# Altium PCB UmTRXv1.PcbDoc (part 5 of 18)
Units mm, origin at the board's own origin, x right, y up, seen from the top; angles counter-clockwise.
Board outline 172 x 113 mm, 6 copper layers (Top Layer, GND, MidLayer1, Mid-Layer 2, InternalPlane2, Bottom Layer); 766 components, 613 nets, 3008 pads, 1360 vias.
Unrouted connection lines stored in the file: 2.
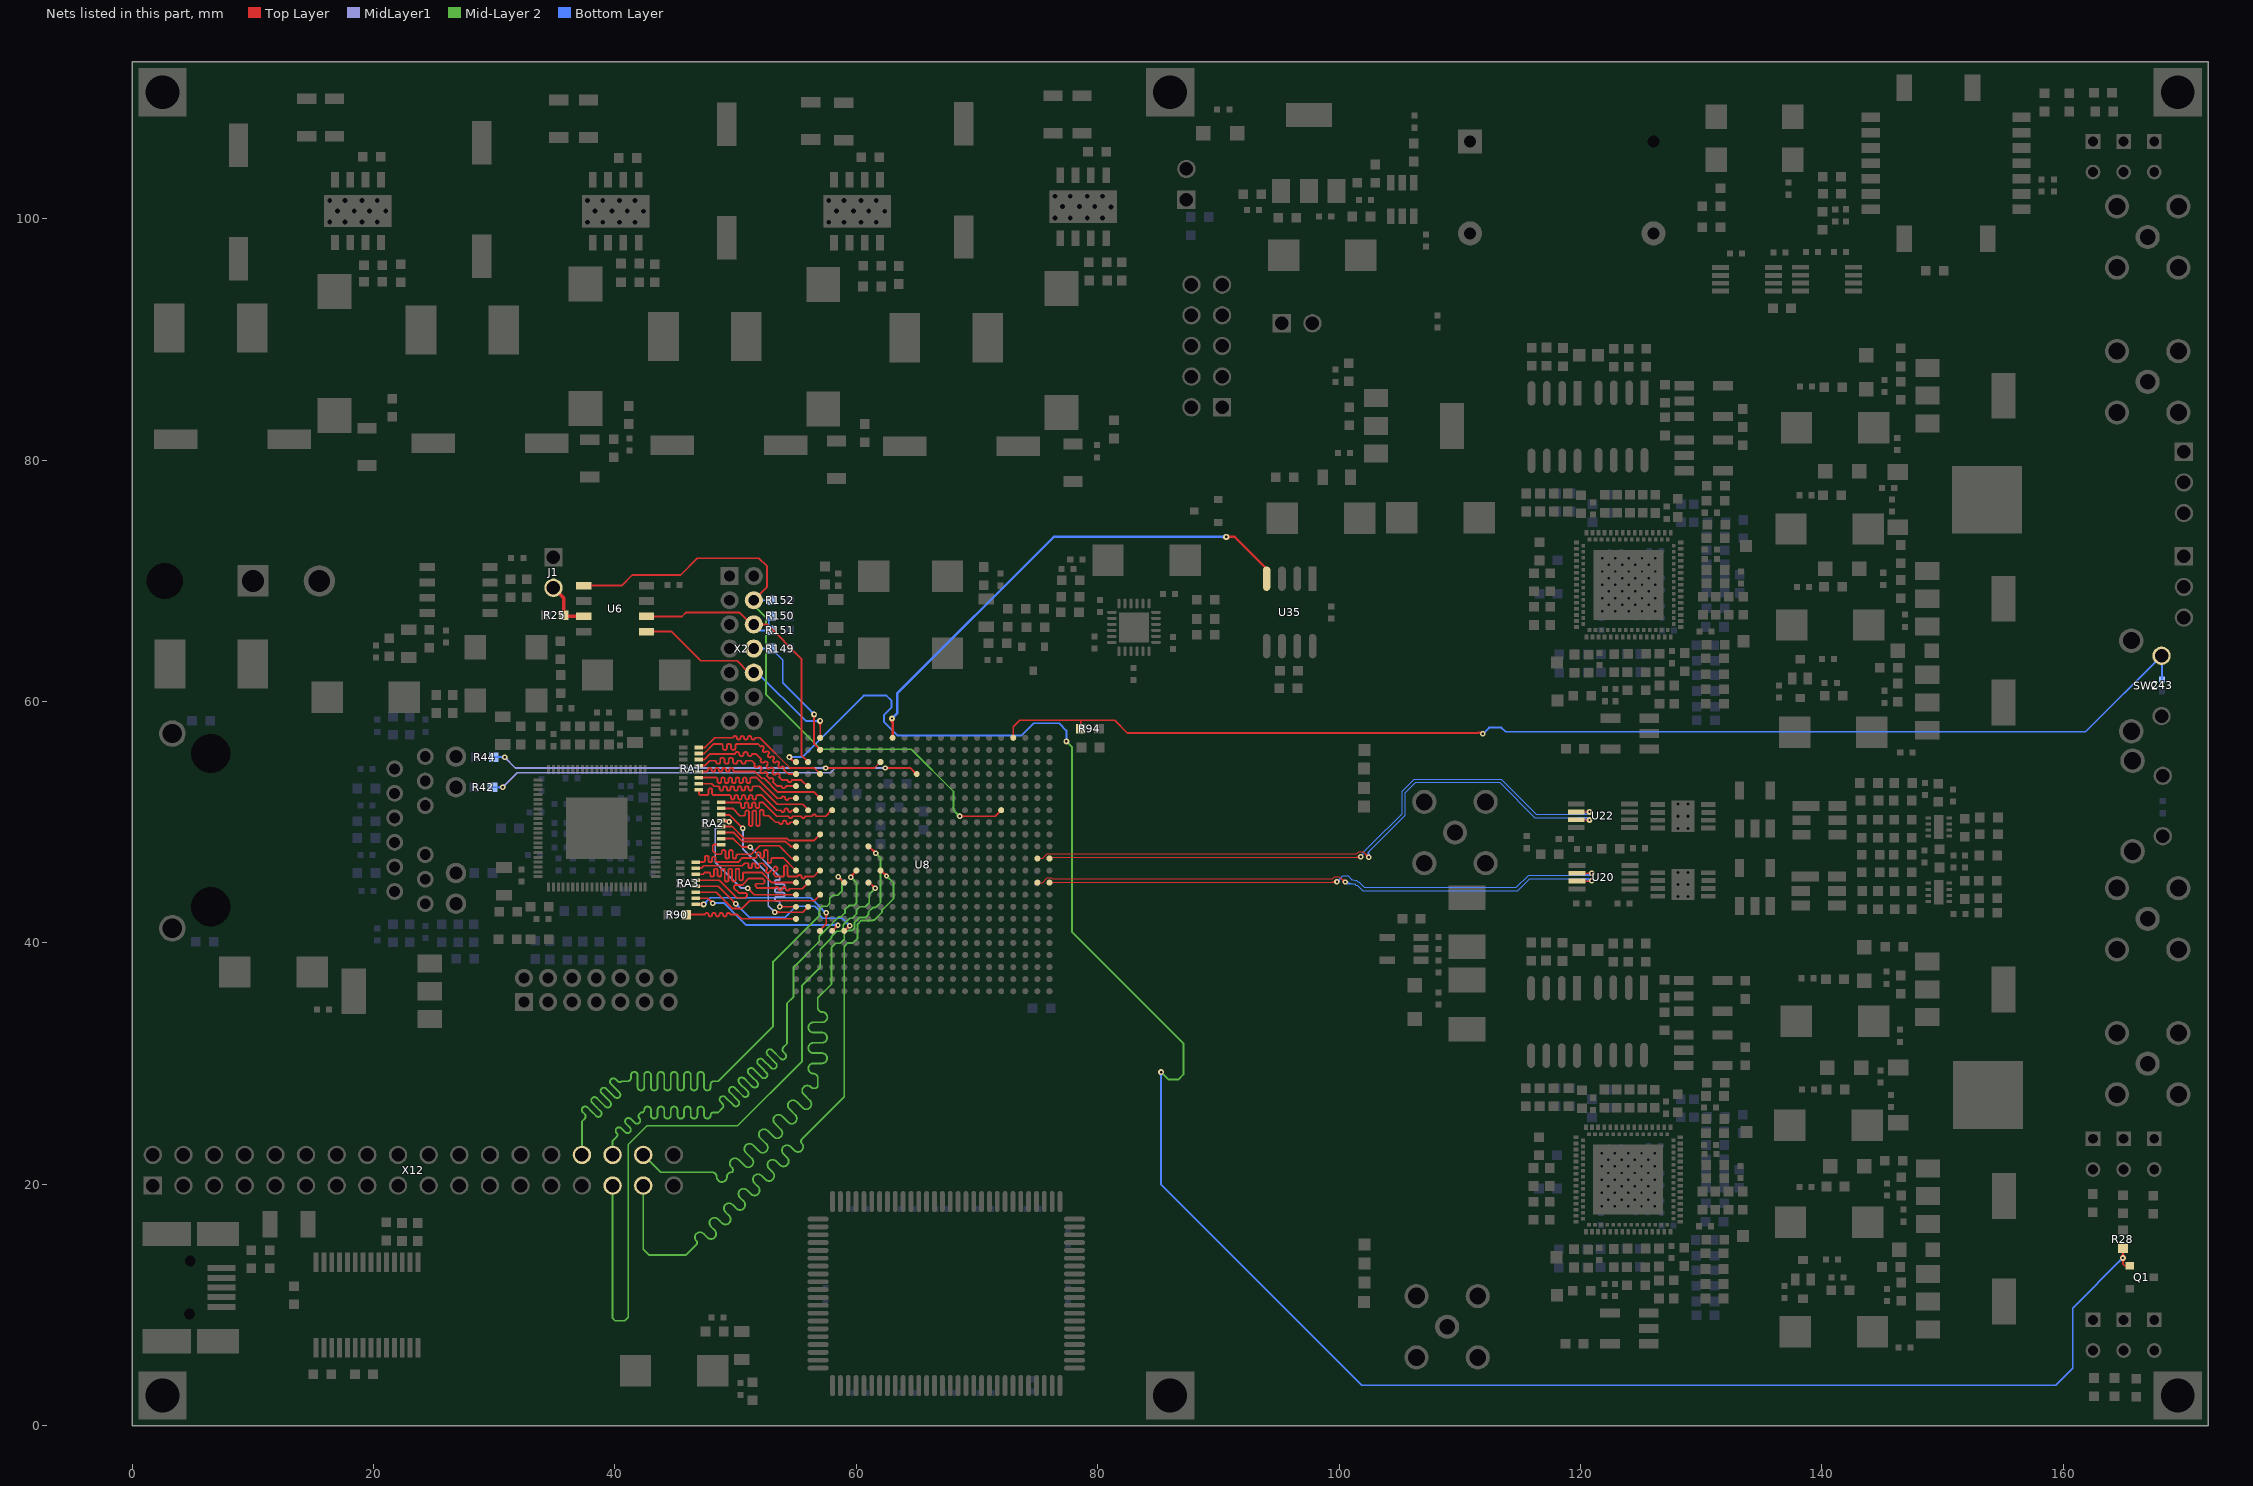
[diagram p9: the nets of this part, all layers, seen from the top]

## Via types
v1: diameter 0.45, hole 0.2, Top Layer to Bottom Layer, tented both sides, 554 vias
v2: diameter 0.5, hole 0.2, Top Layer to Bottom Layer, tented both sides, 468 vias
v3: diameter 0.7, hole 0.3, Top Layer to Bottom Layer, tented both sides, 206 vias
v4: diameter 0.4, hole 0.2, Top Layer to Bottom Layer, tented both sides, 82 vias
v5: diameter 0.8, hole 0.3, Top Layer to Bottom Layer, tented both sides, 16 vias
v6: diameter 0.6, hole 0.25, Top Layer to Bottom Layer, tented both sides, 16 vias
v7: diameter 0.5, hole 0.3, Top Layer to Bottom Layer, tented both sides, 8 vias
v8: diameter 0.7, hole 0.3, Top Layer to Bottom Layer, 4 vias
v9: diameter 0.6, hole 0.3, Top Layer to Bottom Layer, tented both sides, 4 vias
v10: diameter 0.5, hole 0.2, Top Layer to Bottom Layer, 2 vias

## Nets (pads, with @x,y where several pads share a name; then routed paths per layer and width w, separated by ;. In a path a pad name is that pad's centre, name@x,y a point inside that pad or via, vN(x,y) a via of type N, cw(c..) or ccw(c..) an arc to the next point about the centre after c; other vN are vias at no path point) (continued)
DEBUG29: U8.K18 X12.30 | length 63.5
  Top Layer w0.15: v1@58.5,45.35 cw(c58.5,44.988) 58.756,45.244 cw(c59.012,45.5) v1@58.65,45.5 ; v1(58.5,45.5) U8.K18@59,45
  Mid-Layer 2 w0.15: X12.30@37.26,22.44 37.26,25.21 37.489,25.439 ccw(c37.294,25.633) 37.489,25.827 37.332,25.985 cw(c37.526,26.179) 37.332,26.374 cw(c37.526,26.179) 37.72,26.374 38.072,26.022 38.424,25.671 ccw(c38.618,25.865) 38.813,25.671 ccw(c38.618,25.865) 38.813,26.059 38.461,26.411 38.109,26.763 ; 38.109,26.763 cw(c38.304,26.957) 38.109,27.151 cw(c38.304,26.957) 38.498,27.151 39.201,26.448 ; 39.202,26.448 ccw(c39.396,26.643) 39.59,26.448 ccw(c39.396,26.643) 39.591,26.837 38.887,27.54 cw(c39.082,27.735) 38.887,27.929 cw(c39.082,27.735) 39.276,27.929 39.979,27.226 ccw(c40.174,27.421) 40.368,27.226 ccw(c40.174,27.421) 40.368,27.615 39.665,28.318 cw(c39.86,28.513) 39.665,28.707 cw(c39.86,28.513) 40.054,28.707 40.211,28.55 ; 40.211,28.55 ccw(c40.406,28.744) 40.6,28.55 41.05,28.55 ccw(c41.05,28.825) 41.325,28.825 41.325,29.047 cw(c41.6,29.047) 41.6,29.322 cw(c41.6,29.047) 41.875,29.047 41.875,28.053 ccw(c42.15,28.053) 42.15,27.778 ccw(c42.15,28.053) 42.425,28.053 42.425,29.047 cw(c42.7,29.047) 42.7,29.322 cw(c42.7,29.047) 42.975,29.047 42.975,28.053 ccw(c43.25,28.053) 43.25,27.778 ccw(c43.25,28.053) 43.525,28.053 43.525,29.047 cw(c43.8,29.047) 43.8,29.322 cw(c43.8,29.047) 44.075,29.047 44.075,28.053 ccw(c44.35,28.053) 44.35,27.778 ccw(c44.35,28.053) 44.625,28.053 44.625,29.047 cw(c44.9,29.047) 44.9,29.322 cw(c44.9,29.047) 45.175,29.047 45.175,28.053 ccw(c45.45,28.053) 45.45,27.778 ccw(c45.45,28.053) 45.725,28.053 45.725,29.047 cw(c46,29.047) 46,29.322 cw(c46,29.047) 46.275,29.047 46.275,28.053 ccw(c46.55,28.053) 46.55,27.778 ccw(c46.55,28.053) 46.825,28.053 46.825,29.047 cw(c47.1,29.047) 47.1,29.322 cw(c47.1,29.047) 47.375,29.047 47.375,28.053 ccw(c47.65,28.053) 47.65,27.778 ccw(c47.65,28.053) 47.925,28.053 47.925,28.275 cw(c48.2,28.275) 48.2,28.55 48.55,28.55 53.1,33.1 53.1,38.454 56.95,42.304 56.95,42.85 57.15,43.05 57.566,43.05 57.803,43.287 57.803,43.703 58.05,43.95 58.466,43.95 58.8,44.284 58.8,45.2 v1(58.5,45.5) ; v1@58.5,45.35 cw(c58.5,44.988) 58.756,45.244 cw(c59.012,45.5) v1@58.65,45.5
DEBUG30: U8.K16 X12.31 | length 63.4
  Top Layer w0.15: U8.K16@61.05,45.05 v1(61.55,44.55) ; v1@61.4,44.55 ccw(c61.038,44.55) 61.294,44.806 ccw(c61.55,45.062) v1@61.55,44.7
  Mid-Layer 2 w0.15: X12.31@39.8,19.9 39.8,8.9 40,8.7 40.8,8.7 41.1,9 41.1,23.3 42.65,24.85 50.15,24.85 55.5,30.2 55.5,36.5 57,38 57,39.484 57.95,40.434 57.95,40.551 58.378,40.979 58.687,40.979 58.921,41.213 58.921,41.522 59.449,42.05 59.651,42.05 60,42.399 60,42.7 60.3,43 60.75,43 61.075,43.325 61.075,44.025 61.6,44.55 v1(61.55,44.55) ; 61.259,44.209 ccw(c60.917,44.55) v1@61.4,44.55 ; 61.379,44.329 cw(c61.55,44.159) v1@61.55,44.4
DEBUG31: U8.L17 X12.32 | length 62.9
  Top Layer w0.15: v1@59.5,45.45 v1(59.55,45.45) ; v1@59.525,45.525 U8.L17@60,46 ; v1@59.7,45.45 cw(c60.304,45.45) U8.L17@59.877,45.877
  Mid-Layer 2 w0.15: X12.32@39.8,22.44 39.8,23.6 40.135,23.935 ccw(c39.976,24.094) 40.135,24.254 cw(c40.33,24.448) 40.135,24.642 cw(c40.33,24.448) 40.524,24.643 40.842,24.324 ccw(c41.037,24.519) 41.231,24.324 ccw(c41.037,24.519) 41.232,24.713 40.913,25.031 cw(c41.108,25.226) 40.913,25.42 cw(c41.108,25.226) 41.302,25.42 41.62,25.102 ccw(c41.815,25.297) 42.009,25.102 ccw(c41.815,25.297) 42.009,25.491 cw(c42.168,25.65) 42.009,25.809 42.15,25.95 42.2,25.95 ccw(c42.2,26.175) 42.425,26.175 cw(c42.7,26.175) 42.7,26.45 cw(c42.7,26.175) 42.975,26.175 42.975,25.725 ccw(c43.25,25.725) 43.25,25.45 ccw(c43.25,25.725) 43.525,25.725 43.525,26.175 cw(c43.8,26.175) 43.8,26.45 cw(c43.8,26.175) 44.075,26.175 44.075,25.725 ccw(c44.35,25.725) 44.35,25.45 ccw(c44.35,25.725) 44.625,25.725 44.625,26.175 cw(c44.9,26.175) 44.9,26.45 cw(c44.9,26.175) 45.175,26.175 45.175,25.725 ccw(c45.45,25.725) 45.45,25.45 ccw(c45.45,25.725) 45.725,25.725 45.725,26.175 cw(c46,26.175) 46,26.45 cw(c46,26.175) 46.275,26.175 46.275,25.725 ccw(c46.55,25.725) 46.55,25.45 ccw(c46.55,25.725) 46.825,25.725 46.825,26.175 cw(c47.1,26.175) 47.1,26.45 cw(c47.1,26.175) 47.375,26.175 47.375,25.725 ccw(c47.65,25.725) 47.65,25.45 ccw(c47.65,25.725) 47.925,25.725 cw(c48.15,25.725) 48.15,25.95 48.55,25.95 48.9,26.3 ccw(c48.706,26.494) 48.9,26.689 48.75,26.838 cw(c48.945,27.033) 48.75,27.227 cw(c48.945,27.033) 49.139,27.228 ; 49.139,27.227 49.827,26.539 ccw(c50.022,26.734) 50.216,26.539 ccw(c50.022,26.734) 50.216,26.928 ; 50.216,26.928 49.528,27.616 cw(c49.723,27.811) 49.528,28.005 cw(c49.723,27.811) 49.917,28.005 50.605,27.317 ccw(c50.8,27.512) 50.994,27.317 ccw(c50.8,27.512) 50.994,27.706 50.306,28.394 cw(c50.501,28.589) 50.306,28.783 cw(c50.501,28.589) 50.695,28.783 51.039,28.439 51.383,28.095 ccw(c51.577,28.289) 51.772,28.095 ccw(c51.577,28.289) 51.772,28.484 ; 51.473,29.561 51.817,29.217 52.161,28.873 ccw(c52.355,29.067) 52.55,28.873 ccw(c52.355,29.067) 52.55,29.262 52.206,29.606 51.862,29.95 cw(c52.056,30.144) 51.862,30.339 cw(c52.056,30.144) 52.25,30.339 52.939,29.651 ccw(c53.133,29.845) 53.328,29.651 ccw(c53.133,29.845) 53.328,30.039 52.64,30.728 ; 51.473,29.561 ccw(c51.278,29.366) 51.084,29.561 ccw(c51.278,29.366) 51.084,29.172 51.428,28.828 51.772,28.484 ; 52.639,30.728 cw(c52.834,30.922) 52.64,31.116 cw(c52.834,30.922) 53.028,31.117 ; 53.028,31.116 53.716,30.428 ; 53.717,30.428 ccw(c53.911,30.623) 54.105,30.428 ccw(c53.911,30.623) 54.106,30.817 53.956,30.967 cw(c54.15,31.161) 53.956,31.356 54.25,31.65 54.25,35 54.8,35.55 54.8,38 56.925,40.125 56.925,40.55 58.525,42.15 58.716,42.15 59.05,42.484 59.05,42.75 59.4,43.1 59.8,43.1 60,43.3 60,45 v1(59.55,45.45) ; v1@59.55,45.3 cw(c59.55,44.938) 59.806,45.194 cw(c60.062,45.45) v1@59.7,45.45
DEBUG_CLK0: U8.L15 X12.33 | length 63.2
  Top Layer w0.15: U8.L15@62.025,46.025 v1(62.5,45.55) ; v1@62.35,45.55 ccw(c61.988,45.55) 62.244,45.806 ccw(c62.5,46.062) v1@62.5,45.7
  Mid-Layer 2 w0.15: X12.33@42.34,19.9 42.34,14.61 42.8,14.15 45.9,14.15 46.741,14.991 ccw(c46.582,15.151) 46.741,15.31 cw(c47.042,15.61) 46.741,15.911 cw(c47.042,15.61) 47.342,15.911 47.502,15.752 47.656,15.597 ccw(c47.957,15.897) 48.258,15.597 ccw(c47.957,15.897) 48.258,16.198 47.948,16.508 cw(c48.248,16.808) 47.948,17.109 cw(c48.248,16.808) 48.549,17.109 48.704,16.954 48.859,16.799 ccw(c49.159,17.099) 49.46,16.799 ccw(c49.159,17.099) 49.46,17.4 49.15,17.71 cw(c49.45,18.01) 49.15,18.311 cw(c49.45,18.01) 49.751,18.311 49.906,18.156 50.061,18.001 ccw(c50.361,18.301) 50.662,18.001 ccw(c50.361,18.301) 50.662,18.602 50.352,18.912 cw(c50.652,19.212) 50.352,19.513 cw(c50.652,19.212) 50.953,19.513 51.108,19.358 51.263,19.203 ccw(c51.563,19.503) 51.864,19.203 ccw(c51.563,19.503) 51.864,19.804 51.554,20.114 cw(c51.854,20.414) 51.554,20.715 cw(c51.854,20.414) 52.155,20.715 52.31,20.56 52.465,20.405 ccw(c52.765,20.706) 53.066,20.405 ccw(c52.765,20.706) 53.066,21.006 52.756,21.316 cw(c53.057,21.616) 52.756,21.917 cw(c53.057,21.616) 53.357,21.917 53.667,21.607 ccw(c53.967,21.908) 54.268,21.607 ccw(c53.967,21.908) 54.268,22.208 54.113,22.363 53.958,22.518 cw(c54.259,22.818) 53.958,23.119 cw(c54.259,22.818) 54.559,23.119 54.869,22.809 ccw(c55.169,23.11) 55.47,22.809 ccw(c55.169,23.11) 55.474,23.407 ; v1@62.5,45.4 cw(c62.5,45.038) 62.756,45.294 cw(c63.012,45.55) v1@62.65,45.55 ; v1(62.5,45.55) 63.075,44.975 63.075,43.676 62.125,42.726 62.125,42.559 61.466,41.9 61.384,41.9 61.334,41.85 60.384,41.85 60.1,41.566 60.1,40.4 59.7,40 59.3,40 59,39.7 59,27.25 55.474,23.724 ccw(c55.633,23.565) 55.471,23.41 ; 55.471,23.41 ccw(c55.633,23.565) 55.474,23.407 ; 55.471,23.41 cw(c55.169,23.11) 55.474,23.407 ; 55.471,23.41 55.474,23.407
DEBUG_CLK1: U8.N16 X12.34 | length 63.2
  Top Layer w0.15: U8.N16@61.025,48.025 v1(61.6,47.45) ; v1@61.45,47.45 ccw(c61.088,47.45) 61.344,47.706 ccw(c61.6,47.962) v1@61.6,47.6
  Mid-Layer 2 w0.15: X12.34@42.34,22.44 43.78,21 48.05,21 cw(c48.05,20.625) 48.425,20.625 ccw(c48.85,20.625) 48.85,20.2 ccw(c48.85,20.625) 49.275,20.625 cw(c49.65,20.625) 49.65,21 49.7,21 ccw(c49.512,21.188) 49.7,21.376 49.638,21.438 cw(c49.938,21.739) 49.638,22.039 cw(c49.938,21.739) 50.239,22.039 50.739,21.539 ccw(c51.04,21.839) 51.34,21.539 ccw(c51.04,21.839) 51.34,22.14 50.84,22.64 cw(c51.14,22.941) 50.84,23.242 cw(c51.14,22.941) 51.441,23.242 51.942,22.741 ccw(c52.242,23.041) 52.543,22.741 ccw(c52.242,23.041) 52.543,23.342 52.042,23.843 cw(c52.342,24.143) 52.042,24.444 cw(c52.342,24.143) 52.643,24.444 53.144,23.943 ccw(c53.444,24.243) 53.745,23.943 ccw(c53.444,24.243) 53.745,24.544 53.494,24.794 53.244,25.045 cw(c53.544,25.345) 53.244,25.646 cw(c53.544,25.345) 53.845,25.646 54.346,25.145 ccw(c54.646,25.445) 54.947,25.145 ccw(c54.646,25.445) 54.947,25.746 54.446,26.247 cw(c54.746,26.547) 54.446,26.848 cw(c54.746,26.547) 55.047,26.848 55.548,26.347 ccw(c55.848,26.648) 56.149,26.347 ccw(c55.848,26.648) 56.149,26.948 55.633,27.464 cw(c55.934,27.764) 55.633,28.065 cw(c55.934,27.764) 56.234,28.065 ccw(c56.499,28.33) 56.765,28.065 56.8,28.1 56.8,28.8 ccw(c56.425,28.8) 56.425,29.175 ; 56.429,29.175 56.442,29.175 ; 56.446,29.175 cw(c56.446,29.6) 56.021,29.6 cw(c56.446,29.6) 56.446,30.025 57.154,30.025 ccw(c57.154,30.45) 57.579,30.45 ccw(c57.154,30.45) 57.154,30.875 56.446,30.875 cw(c56.446,31.3) 56.021,31.3 cw(c56.446,31.3) 56.446,31.725 57.154,31.725 ccw(c57.154,32.15) 57.579,32.15 ccw(c57.154,32.15) 57.154,32.575 56.446,32.575 cw(c56.446,33) 56.021,33 cw(c56.446,33) 56.446,33.425 57.175,33.425 ccw(c57.175,33.85) 57.6,33.85 ccw(c57.175,33.85) 57.175,34.275 cw(c57.175,34.65) 56.8,34.65 56.8,35.45 57.95,36.6 57.95,39.64 58.285,39.975 58.676,39.975 59,40.299 59,40.85 59.175,41.025 59.616,41.025 59.85,41.259 59.85,41.7 60.25,42.1 60.75,42.1 61,42.35 61,42.566 61.384,42.95 61.6,42.95 62,43.35 62,47.05 v1(61.6,47.45) ; v1@61.6,47.3 cw(c61.6,46.938) 61.856,47.194 cw(c62.112,47.45) v1@61.75,47.45
DIVSW1_N: U8.K1 U20.6 | length 51.1
  Top Layer w0.1: U8.K1@76,45 76.05,45.05 v1@99.813,45.05 ; 99.377,45.05 ccw(c99.377,45.507) v1@99.7,45.184 ; 99.425,45.05 cw(c99.425,44.662) v1@99.7,44.936 ; U20.6@119.701,45.781 120.94,45.781 v1(120.95,45.771) ; 120.503,45.781 cw(c120.503,45.324) v1@120.826,45.647 ; 120.552,45.781 ccw(c120.552,46.169) v1@120.826,45.895
  Bottom Layer w0.1: v1(99.823,45.06) 100.313,45.55 100.75,45.55 101.056,45.244 101.231,45.244 101.279,45.195 101.279,45.205 101.405,45.205 101.55,45.06 101.616,45.06 102.076,44.6 114.7,44.6 115.696,45.596 120.775,45.596 v1(120.95,45.771) ; v1@99.823,45.235 ccw(c99.823,45.657) 100.122,45.359 ccw(c100.421,45.06) v1@99.998,45.06 ; 120.105,45.596 ccw(c120.105,46.616) v1@120.826,45.895 ; 120.346,45.596 ccw(c120.346,46.374) v1@120.897,45.824 ; 120.588,45.596 ccw(c120.588,46.133) v1@120.968,45.753
DIVSW1_P: U8.K2 U20.7 | length 53.6
  Top Layer w0.1: U8.K2@75,45 75.434,45 75.834,45.4 76.166,45.4 76.236,45.33 99.48,45.33 99.65,45.5 100.033,45.5 100.483,45.05 v1(100.5,45.05) ; 100.173,45.36 ccw(c100.5,45.687) v1@100.5,45.225 ; 100.213,45.321 cw(c99.942,45.05) v1@100.325,45.05 ; U20.7@119.701,45.131 120.94,45.131 v1(120.95,45.141) ; 120.503,45.131 ccw(c120.503,45.587) v1@120.826,45.265 ; 120.552,45.131 cw(c120.552,44.742) v1@120.826,45.017
  Bottom Layer w0.1: v1@100.482,45.032 ccw(c100.796,45.347) 100.796,44.902 ; v1@100.553,45.103 ccw(c101.038,45.588) 101.038,44.902 ; v1@100.624,45.174 ccw(c101.279,45.829) 101.279,44.902 ; 120.105,45.316 cw(c120.105,44.296) v1@120.826,45.017 ; 120.346,45.316 cw(c120.346,44.537) v1@120.897,45.088 ; 120.588,45.316 cw(c120.588,44.779) v1@120.968,45.158 ; v1@120.879,45.07 v1(120.95,45.141) 120.775,45.316 115.816,45.316 114.82,44.32 101.96,44.32 101.5,44.78 101.4,44.78 101.278,44.902 100.631,44.902 v1@100.483,45.05 ; v1@100.483,45.05 100.413,45.12 100.413,45.136 v1(100.5,45.05) v1@100.483,45.05
DIVSW2_N: U8.M1 U22.6 | length 55.4
  Top Layer w0.1: U8.M1@76,47 76.1,47.1 v1@101.793,47.1 ; 101.299,47.1 ccw(c101.299,47.625) v1@101.67,47.254 ; 101.443,47.1 cw(c101.443,46.78) v1@101.67,47.006 ; 101.54,47.1 ccw(c101.54,47.383) v1@101.74,47.183 ; U22.6@119.651,50.856 120.735,50.856 v2(120.75,50.871) ; U22.6@120.231,50.856 ccw(c120.231,51.39) v2@120.609,51.012 ; U22.6@120.303,50.856 cw(c120.303,50.424) v2@120.609,50.729 ; 120.472,50.856 ccw(c120.472,51.148) v2@120.679,50.941
  Bottom Layer w0.1: v1(101.793,47.13) 102,47.337 102,47.5 102.675,48.175 105.22,50.72 105.22,52.566 106.234,53.58 113.42,53.58 116.329,50.671 120.55,50.671 v2(120.75,50.871) cw(c120.267,51.354) 120.267,50.671 ; 119.784,50.671 ccw(c119.784,51.836) v2@120.609,51.012 ; 120.026,50.671 ccw(c120.026,51.595) v2@120.679,50.941 ; 120.509,50.671 ccw(c120.509,51.112) v2@120.821,50.8
DIVSW2_P: U8.M2 U22.7 | length 57.3
  Top Layer w0.1: U8.M2@75,47 75.434,47 75.834,47.4 76.166,47.4 76.186,47.38 101.45,47.38 ; 101.45,47.4 101.62,47.57 102.003,47.57 102.45,47.124 v1(102.45,47.1) ; 102.134,47.439 cw(c101.795,47.1) v1@102.275,47.1 ; 102.191,47.382 ccw(c102.45,47.64) v1@102.45,47.275 ; U22.7@119.651,50.206 120.735,50.206 v2(120.75,50.191) ; U22.7@120.231,50.206 cw(c120.231,49.672) v2@120.609,50.049 ; U22.7@120.303,50.206 ccw(c120.303,50.637) v2@120.609,50.332 ; 120.472,50.206 cw(c120.472,49.913) v2@120.679,50.12
  Bottom Layer w0.1: v1@102.326,47.224 ccw(c102.067,47.483) 102.433,47.483 ; v1(102.45,47.1) 102.45,47.124 102.433,47.14 102.433,47.537 ; v1@102.569,47.228 cw(c102.854,47.537) 102.433,47.537 ; 119.784,50.391 cw(c119.784,49.225) v2@120.609,50.049 ; 120.026,50.391 cw(c120.026,49.467) v2@120.679,50.12 ; 120.267,50.391 cw(c120.267,49.708) v2(120.75,50.191) 120.55,50.391 116.213,50.391 113.304,53.3 106.35,53.3 105.5,52.45 105.5,50.604 104.698,49.802 102.433,47.537 ; 120.509,50.391 cw(c120.509,49.949) v2@120.821,50.261
DONE: Q1.1 R28.2 U8.Y22 | length 172.9
  Top Layer w0.15: v2@54.45,55.225 cw(c54.45,54.803) 54.749,55.101 cw(c55.047,55.4) v2@54.625,55.4 ; v2(54.45,55.4) 54.85,55 U8.Y22@55,55 ; v2@164.826,13.776 cw(c164.528,13.478) 164.95,13.478 cw(c165.372,13.478) v2@165.074,13.776 ; v2@164.826,14.024 ccw(c164.528,14.322) 164.95,14.322 ccw(c165.372,14.322) v2@165.074,14.024 ; R28.2@164.95,14.7 v2(164.95,13.9) 164.95,13.4 165.1,13.25 Q1.1@165.5,13.25
  Mid-Layer 2 w0.15: v10(77.4,56.7) 77.856,56.244 77.856,40.918 87.1,31.674 87.1,29.1 86.7,28.7 85.85,28.7 v2(85.25,29.3)
  Bottom Layer w0.15: v2(54.45,55.4) 55.5,55.4 60.6,60.5 62.5,60.5 62.9,60.1 62.9,59.5 62.3,58.9 62.3,58.3 63.4,57.2 73.7,57.2 74.7,58.2 76.8,58.2 77.4,57.6 v10(77.4,56.7) ; v2@85.126,29.176 cw(c84.828,28.878) 85.25,28.878 cw(c85.672,28.878) v2@85.374,29.176 ; v2(85.25,29.3) 85.25,28.35 85.25,19.965 101.865,3.35 159.4,3.35 160.8,4.75 160.8,9.75 v2(164.95,13.9) ; v2@164.775,13.9 cw(c164.353,13.9) 164.651,13.601 cw(c164.95,13.303) v2@164.95,13.725
ETH_LEDG: R44.2 U8.Y15 | length 34.9
  Top Layer w0.15: v1(57.45,54.5) 61.5,54.5 U8.Y15@62,55 ; v1@57.556,54.394 cw(c57.812,54.138) 57.812,54.5 cw(c57.812,54.862) v1@57.556,54.606
  MidLayer1 w0.15: v1@30.85,55.25 cw(c30.85,54.888) 31.106,55.144 cw(c31.362,55.4) v1@31,55.4 ; v1(30.85,55.4) 31.75,54.5 v1(57.45,54.5) ; v1@57.344,54.394 ccw(c57.088,54.138) 57.088,54.5 ccw(c57.088,54.862) v1@57.344,54.606
  Bottom Layer w0.15: R44.2@29.95,55.4 v1(30.85,55.4) ; v1@30.744,55.294 ccw(c30.488,55.038) 30.488,55.4 ccw(c30.488,55.762) v1@30.744,55.506
ETH_LEDO: R42.2 U8.W12 | length 39
  Top Layer w0.15: v1(62.4,54.5) 64.45,54.5 ; v1@62.506,54.394 cw(c62.762,54.138) 62.762,54.5 cw(c62.762,54.862) v1@62.506,54.606 ; U8.W12@64.975,53.975 64.45,54.5 ; U8.W12@65,54 64.5,54.5 64.45,54.5
  MidLayer1 w0.15: v1(30.7,52.9) 31.9,54.1 57.85,54.1 58.25,54.5 v1(62.4,54.5) ; v1@30.7,53.05 ccw(c30.7,53.412) 30.956,53.156 ccw(c31.212,52.9) v1@30.85,52.9 ; v1@62.294,54.394 ccw(c62.038,54.138) 62.038,54.5 ccw(c62.038,54.862) v1@62.294,54.606
  Bottom Layer w0.15: R42.2@29.85,52.9 v1(30.7,52.9) ; v1@30.594,52.794 ccw(c30.338,52.538) 30.338,52.9 ccw(c30.338,53.262) v1@30.594,53.006
FAN_ON: U8.AB14 U35.4 | length 43.4
  Top Layer w0.2: v2@62.844,58.494 cw(c62.467,58.117) 63,58.117 ; v2(62.95,58.6) 63,58.65 U8.AB14@63,57 ; v2(90.65,73.65) 91.35,73.65 93.995,71.005 U35.4@93.995,70.191 ; v2@90.756,73.544 cw(c91.012,73.288) 91.012,73.65 cw(c91.012,74.012) v2@90.756,73.756
  Bottom Layer w0.2: v2(62.95,58.6) 63.4,59.05 63.4,60.7 76.35,73.65 v2(90.65,73.65) ; v2@90.544,73.544 ccw(c90.288,73.288) 90.288,73.65 ccw(c90.288,74.012) v2@90.544,73.756
FLASH_CLK: R150.2 R151.2 U6.6 U8.Y21 X2.6 | length 25.6
  Top Layer w0.15: U6.6@42.6,67.05 45.55,67.05 45.895,67.395 50.305,67.395 51,66.7 X2.6@51,66.5 ; X2.6@51.1,66.4 X2.6@51.5,66.4 52.6,66.4 55.45,63.55 55.45,55.55 U8.Y21@56,55
  Bottom Layer w0.15: X2.6@51.707,65.893 52.741,65.893 52.734,65.899 R150.2@52.734,67.133
FLASH_CS: R152.2 U6.1 U8.T5 X2.4 | length 56.1
  Top Layer w0.15: U6.1@37.401,69.609 40.555,69.609 41.439,70.492 45.442,70.492 46.822,71.872 51.928,71.872 52.6,71.2 52.6,69.5 X2.4@51.5,68.4 X2.4@51.1,68.4 ; v1(68.55,50.5) 71.5,50.5 U8.T5@72,51 ; v1@68.674,50.376 cw(c68.972,50.078) 68.972,50.5 cw(c68.972,50.922) v1@68.674,50.624
  Mid-Layer 2 w0.15: X2.4@51.1,68.4 52.5,67 52.5,60.6 57.05,56.05 64.551,56.05 68.05,52.551 68.05,51 v1(68.55,50.5) ; v1@68.375,50.5 ccw(c67.953,50.5) 68.251,50.799 ccw(c68.55,51.097) v1@68.55,50.675
  Bottom Layer w0.15: X2.4@51.1,68.4 X2.4@51.5,68.4 R152.2@52.65,68.4
FLASH_MISO: R149.1 U8.AA20 X2.8 | length 13
  Top Layer w0.15: v2@56.376,58.826 cw(c56.078,58.528) 56.5,58.528 cw(c56.922,58.528) v2@56.624,58.826 ; v2(56.5,58.95) 56.5,56.5 U8.AA20@57,56
  Bottom Layer w0.15: R149.1@52.95,64.4 53.9,63.45 53.9,61.55 v2(56.5,58.95) ; v2@56.325,58.95 ccw(c55.903,58.95) 56.201,59.249 ccw(c56.5,59.547) v2@56.5,59.125
  Bottom Layer w0.2: X2.8@51.2,64.4 X2.8@51.5,64.4 R149.1@52.75,64.4
FLASH_MOSI: U6.5 U8.AB20 X2.10 | length 20.2
  Top Layer w0.15: U6.5@42.611,65.8 44.7,65.8 47.121,63.379 50.121,63.379 X2.10@51.1,62.4 ; v2@56.876,58.276 cw(c56.578,57.978) 57,57.978 cw(c57.422,57.978) v2@57.124,58.276 ; U8.AB20@57,57 v2(57,58.4)
  Bottom Layer w0.15: X2.10@51.1,62.4 X2.10@51.5,62.4 51.8,62.4 55.8,58.4 v2(57,58.4) ; v2@56.876,58.276 ccw(c56.578,57.978) 56.578,58.4 ccw(c56.578,58.822) v2@56.876,58.524
FLASH_WP: J1.2 R25.1 U6.3 | length 4.6
  Top Layer w0.3: J1.2@34.9,69.43 35.75,68.58 R25.1@35.75,67.15 ; R25.1@35.55,67.25 35.731,67.069 U6.3@37.401,67.069
FPGA_RESET: C43.2 R94.2 SW2.2 U8.AB4 | length 102.7
  Top Layer w0.15: U8.AB4@73,57 73,57.9 73.55,58.45 78.6,58.45 ; R94.2@78.6,57.75 78.6,58.45 ; v1@111.758,57.301 ccw(c111.55,57.23) 111.55,57.45 ; v1(111.9,57.35) 111.8,57.45 111.55,57.45 ; 78.6,58.45 81.4,58.45 82.45,57.4 111.5,57.4 111.55,57.45
  Bottom Layer w0.15: v1(111.9,57.35) 111.931,57.35 112.431,57.85 113.45,57.85 113.8,57.5 161.85,57.5 SW2.2@168.15,63.8 168.2,63.75 C43.2@168.2,61.85
GMII_COL: RA2.11 U8.N22 | length 6.7
  Top Layer w0.15: RA2.11@48.8,49.15 49.85,49.15 50.6,48.4 54.15,48.4 54.55,48 U8.N22@55,48
GMII_CRS: RA2.12 U8.P20 | length 8.9
  Top Layer w0.15: RA2.12@48.8,49.65 49.704,49.65 50.704,48.65 54.254,48.65 54.404,48.5 56.5,48.5 U8.P20@57,49
GMII_GTX_CLK: RA2.14 U8.H21 | length 15.3
  Top Layer w0.15: RA2.14@48.85,50.6 49.5,50.6 v1@50.5,49.6 ; v1@50.45,49.5 ccw(c50.088,49.5) 50.344,49.756 ccw(c50.6,50.012) v1@50.6,49.65 ; v1(53.25,42.55) 55.55,42.55 U8.H21@56,43 ; v1@53.356,42.444 cw(c53.612,42.188) 53.612,42.55 cw(c53.612,42.912) v1@53.356,42.656
  MidLayer1 w0.15: v1@50.494,49.394 cw(c50.238,49.138) 50.6,49.138 cw(c50.962,49.138) v1@50.706,49.394 ; v1@50.6,49.45 50.6,47.8 52.7,45.7 52.7,43.1 v1(53.25,42.55) ; v1@53.1,42.55 ccw(c52.738,42.55) 52.994,42.806 ccw(c53.25,43.062) v1@53.25,42.7
  other v1: 50.6,49.5
GMII_RX_CLK: RA2.10 U8.H22 | length 15.5
  Top Layer w0.15: RA2.10@48.8,48.65 49.8,48.65 50.5,47.95 v1(51.2,47.95) ; v1@51.094,47.844 ccw(c50.838,47.588) 50.838,47.95 ccw(c50.838,48.312) v1@51.094,48.056 ; v1(53.65,43) U8.H22@55,43 ; v1@53.756,42.894 cw(c54.012,42.638) 54.012,43 cw(c54.012,43.362) v1@53.756,43.106
  MidLayer1 w0.15: v1@51.2,47.8 cw(c51.2,47.438) 51.456,47.694 cw(c51.712,47.95) v1@51.35,47.95 ; v1(51.2,47.95) 53.65,45.5 53.65,45.25 cw(c53.625,45.25) 53.625,45.225 53.39,45.225 ccw(c53.39,45.085) 53.25,45.085 53.25,45.015 ccw(c53.39,45.015) 53.39,44.875 53.91,44.875 cw(c53.91,44.735) 54.05,44.735 54.05,44.665 cw(c53.91,44.665) 53.91,44.525 53.39,44.525 ccw(c53.39,44.385) 53.25,44.385 53.25,44.315 ccw(c53.39,44.315) 53.39,44.175 53.91,44.175 cw(c53.91,44.035) 54.05,44.035 54.05,43.965 cw(c53.91,43.965) 53.91,43.825 53.39,43.825 ccw(c53.39,43.685) 53.25,43.685 53.25,43.615 ccw(c53.39,43.615) 53.39,43.475 53.51,43.475 cw(c53.51,43.335) 53.65,43.335 ; v1@53.55,43.112 ccw(c53.351,43.335) 53.65,43.335 ; v1(53.65,43) 53.65,43.335 ; v1@53.75,43.112 cw(c53.949,43.335) 53.65,43.335
GMII_RX_DV: RA3.16 U8.L22 | length 12.9
  Top Layer w0.15: RA3.16@46.7,46.7 47.33,46.7 ccw(c47.33,46.82) 47.45,46.82 47.45,47.103 cw(c47.57,47.103) 47.57,47.223 47.63,47.223 cw(c47.63,47.103) 47.75,47.103 47.75,46.82 ccw(c47.87,46.82) 47.87,46.7 47.93,46.7 ccw(c47.93,46.82) 48.05,46.82 48.05,47.021 cw(c48.17,47.021) 48.17,47.141 48.23,47.141 cw(c48.23,47.021) 48.35,47.021 48.35,46.82 ccw(c48.47,46.82) 48.47,46.7 50.2,46.7 50.55,47.05 51.63,47.05 ccw(c51.63,47.17) 51.75,47.17 51.75,47.397 cw(c51.87,47.397) 51.87,47.517 51.93,47.517 cw(c51.93,47.397) 52.05,47.397 52.05,47.17 ccw(c52.17,47.17) 52.17,47.05 52.23,47.05 ccw(c52.23,47.17) 52.35,47.17 52.35,47.58 cw(c52.47,47.58) 52.47,47.7 52.53,47.7 cw(c52.53,47.58) 52.65,47.58 52.65,46.753 ccw(c52.77,46.753) 52.77,46.633 52.83,46.633 ccw(c52.83,46.753) 52.95,46.753 52.95,46.93 cw(c53.07,46.93) 53.07,47.05 53.95,47.05 U8.L22@55,46
GMII_RX_ER: RA2.9 U8.M22 | length 11.1
  Top Layer w0.15: RA2.9@48.8,48.15 48.2,48.15 48.1,48.05 48.1,47.65 48.4,47.35 48.7,47.35 ccw(c48.7,47.5) 48.85,47.5 48.85,47.56 cw(c49,47.56) 49,47.71 cw(c49,47.56) 49.15,47.56 49.15,47.14 ccw(c49.3,47.14) 49.3,46.99 ccw(c49.3,47.14) 49.45,47.14 49.45,47.56 cw(c49.6,47.56) 49.6,47.71 cw(c49.6,47.56) 49.75,47.56 49.75,47.14 ccw(c49.9,47.14) 49.9,46.99 ccw(c49.9,47.14) 50.05,47.14 50.05,47.2 cw(c50.2,47.2) 50.2,47.35 51.3,47.35 52,48.05 53.6,48.05 54.65,47 U8.M22@55,47
GMII_RXD0: RA3.15 U8.L20 | length 15.8
  Top Layer w0.15: RA3.15@46.7,46.2 47.15,46.2 47.35,46.4 50.55,46.4 50.75,46.6 51,46.6 cw(c51,46.55) 51.05,46.55 51.05,46.32 ccw(c51.17,46.32) 51.17,46.2 51.23,46.2 ccw(c51.23,46.32) 51.35,46.32 51.35,46.48 cw(c51.47,46.48) 51.47,46.6 51.53,46.6 cw(c51.53,46.48) 51.65,46.48 51.65,46.32 ccw(c51.77,46.32) 51.77,46.2 51.83,46.2 ccw(c51.83,46.32) 51.95,46.32 51.95,46.48 cw(c52.07,46.48) 52.07,46.6 52.235,46.6 52.583,46.252 cw(c52.498,46.167) 52.583,46.082 52.541,46.04 ccw(c52.626,45.955) 52.541,45.87 52.583,45.827 ccw(c52.668,45.912) 52.753,45.827 53.222,46.297 ; 53.222,46.297 cw(c53.307,46.212) 53.392,46.297 53.434,46.254 ; 53.435,46.254 cw(c53.35,46.169) 53.434,46.084 53.177,45.827 ccw(c53.262,45.743) 53.177,45.658 53.335,45.5 53.88,45.5 ccw(c53.88,45.62) 54,45.62 54,46.297 cw(c54.12,46.297) 54.12,46.417 54.18,46.417 cw(c54.18,46.297) 54.3,46.297 54.3,45.62 ccw(c54.42,45.62) 54.42,45.5 55.15,45.5 cw(c55.3,45.5) 55.45,45.5 ccw(c55.6,45.5) 55.75,45.5 56.45,45.5 U8.L20@56.975,46.025
GMII_RXD1: RA3.14 U8.K22 | length 15.8
  Top Layer w0.15: RA3.14@46.7,45.7 47.3,45.7 47.45,45.85 47.78,45.85 cw(c47.78,45.73) 47.9,45.73 47.9,45.626 ccw(c48.02,45.626) 48.02,45.506 48.08,45.506 ccw(c48.08,45.626) 48.2,45.626 48.2,46.03 cw(c48.32,46.03) 48.32,46.15 48.38,46.15 cw(c48.38,46.03) 48.5,46.03 48.5,45.626 ccw(c48.62,45.626) 48.62,45.506 48.68,45.506 ccw(c48.68,45.626) 48.8,45.626 48.8,46.03 cw(c48.92,46.03) 48.92,46.15 48.98,46.15 cw(c48.98,46.03) 49.1,46.03 49.1,45.21 ccw(c49.22,45.21) 49.22,45.09 49.28,45.09 ccw(c49.28,45.21) 49.4,45.21 49.4,46.03 cw(c49.52,46.03) 49.52,46.15 49.58,46.15 cw(c49.58,46.03) 49.7,46.03 49.7,45.22 ccw(c49.82,45.22) 49.82,45.1 49.88,45.1 ccw(c49.88,45.22) 50,45.22 50,46.03 cw(c50.12,46.03) 50.12,46.15 50.18,46.15 cw(c50.18,46.03) 50.3,46.03 50.3,45.31 ccw(c50.42,45.31) 50.42,45.19 50.48,45.19 ccw(c50.48,45.31) 50.6,45.31 50.6,45.73 cw(c50.72,45.73) 50.72,45.85 52.15,45.85 53,45 U8.K22@55,45
GMII_RXD2: RA3.13 U8.K21 | length 15.8
  Top Layer w0.15: RA3.13@46.7,45.2 48.65,45.2 50.1,43.75 50.8,43.75 50.95,43.9 50.95,44.05 50.85,44.15 50.25,44.15 49.85,44.55 49.85,44.7 49.95,44.8 50.55,44.8 51.1,45.35 52.2,45.35 52.4,45.15 52.4,45 52.3,44.9 51.7,44.9 51.65,44.85 51.65,44.7 51.8,44.55 53.249,44.55 53.333,44.634 cw(c53.4,44.5) 53.55,44.5 ccw(c53.7,44.5) 53.85,44.5 cw(c54,44.5) 54.15,44.5 ccw(c54.3,44.5) 54.45,44.5 55.5,44.5 U8.K21@56,45
GMII_RXD3: RA3.12 U8.F18 | length 18
  Top Layer w0.15: RA3.12@46.7,44.7 48.55,44.7 v1(50,43.25) ; v1@49.85,43.25 ccw(c49.488,43.25) 49.744,43.506 ccw(c50,43.762) v1@50,43.4 ; U8.F18@59,41 59.45,41.45 v1(59.45,41.425) ; U8.F18@59.151,41.151 cw(c59.45,40.853) v1@59.45,41.275 ; 59.212,41.212 ccw(c58.998,41.425) v1@59.3,41.425
  Bottom Layer w0.15: v1@50,43.1 cw(c50,42.738) 50.256,42.994 cw(c50.512,43.25) v1@50.15,43.25 ; v1(50,43.25) 51.15,42.1 54.05,42.1 55,43.05 56.551,43.05 56.925,42.676 56.925,42.475 56.95,42.45 56.95,42.3 57.2,42.05 58.825,42.05 v1(59.45,41.425) ; 59.194,41.681 cw(c58.938,41.425) v1@59.3,41.425 ; 59.194,41.681 ccw(c59.45,41.937) v1@59.45,41.575
GMII_RXD4: RA3.11 U8.J20 | length 11.3
  Top Layer w0.15: RA3.11@46.7,44.2 48.4,44.2 49.75,42.85 50.5,42.85 51.15,43.5 56.5,43.5 U8.J20@57,44
GMII_RXD5: RA3.10 U8.F19 | length 15.7
  Top Layer w0.15: RA3.10@46.7,43.7 47.7,43.7 v1(48.1,43.3) ; v1@47.95,43.3 ccw(c47.588,43.3) 47.844,43.556 ccw(c48.1,43.812) v1@48.1,43.45 ; U8.F19@58,41 58.45,41.45 v1@58.521,41.379 ; U8.F19@58.159,41.159 ccw(c57.817,41.5) v1@58.3,41.5 ; 58.279,41.279 cw(c58.45,41.109) v1@58.45,41.35
  Bottom Layer w0.15: v1(48.1,43.3) 49.05,43.3 50.85,41.5 58.455,41.5 v1(58.478,41.477) ; v1@48.206,43.194 cw(c48.462,42.938) 48.462,43.3 cw(c48.462,43.662) v1@48.206,43.406 ; v1@58.344,41.394 ccw(c58.088,41.138) 58.088,41.5 ccw(c58.088,41.862) v1@58.344,41.606
GMII_RXD6: RA3.9 U8.F20 | length 15.7
  Top Layer w0.15: RA3.9@46.7,43.2 v2(47.35,43.2) ; v2@47.226,43.076 ccw(c46.928,42.778) 46.928,43.2 ccw(c46.928,43.622) v2@47.226,43.324 ; U8.F20@57,41 57,41.1 57.5,41.6 v1(57.5,42.5) ; v1@57.394,42.394 cw(c57.138,42.138) 57.5,42.138 cw(c57.862,42.138) v1@57.606,42.394
  Bottom Layer w0.15: v2(47.35,43.2) 47.9,43.75 56.205,43.75 57.175,42.78 57.175,42.756 ; v2@47.35,43.375 ccw(c47.35,43.797) 47.649,43.499 ccw(c47.947,43.2) v2@47.525,43.2 ; 57.293,42.638 cw(c57.155,42.5) v1@57.35,42.5 ; v1@57.482,42.649 cw(c57.439,43.02) 57.175,42.756 ; v1(57.5,42.5) 57.431,42.5 57.175,42.756
GMII_RXD7: R90.1 U8.G22 | length 10.4
  Top Layer w0.15: R90.1@45.9,42.35 47.45,42.35 cw(c47.6,42.35) 47.75,42.35 ccw(c47.9,42.35) 48.05,42.35 cw(c48.2,42.35) 48.35,42.35 ccw(c48.5,42.35) 48.65,42.35 cw(c48.8,42.35) 48.95,42.35 ccw(c49.1,42.35) 49.25,42.35 cw(c49.4,42.35) 49.55,42.35 50.15,42.35 50.5,42 U8.G22@55,42
GMII_TX_CLK: RA2.13 U8.J22 | length 15.2
  Top Layer w0.15: RA2.13@48.8,50.15 v1@49.55,50.15 ; RA2.13@48.846,50.15 cw(c48.846,49.446) v1@49.344,49.944 ; 49.209,50.15 cw(c49.209,49.809) v1(49.45,50.05) ; v1@51,44.4 cw(c51,44.038) 51.256,44.294 cw(c51.512,44.55) v1@51.15,44.55 ; v1(51,44.55) 51.55,44 U8.J22@55,44
  MidLayer1 w0.15: v1@49.323,49.971 ccw(c49,49.77) 49,50.15 ; v1@49.55,50.15 49,50.15 ; v1@50.894,44.444 ccw(c50.638,44.188) 50.638,44.55 ccw(c50.638,44.912) v1@50.894,44.656 ; v1(51,44.55) 50.45,44.55 48.3,46.7 48.3,49.45 49,50.15
GMII_TX_EN: RA2.16 U8.T19 | length 12.5
  Top Layer w0.15: RA2.16@48.8,51.65 48.821,51.629 50.33,51.629 cw(c50.33,51.509) 50.45,51.509 50.45,51.299 ccw(c50.57,51.299) 50.57,51.179 50.63,51.179 ccw(c50.63,51.299) 50.75,51.299 50.75,51.509 cw(c50.87,51.509) 50.87,51.629 50.93,51.629 cw(c50.93,51.509) 51.05,51.509 51.05,51.299 ccw(c51.17,51.299) 51.17,51.179 51.23,51.179 ccw(c51.23,51.299) 51.35,51.299 51.35,51.509 cw(c51.47,51.509) 51.47,51.629 51.53,51.629 cw(c51.53,51.509) 51.65,51.509 51.65,51.299 ccw(c51.77,51.299) 51.77,51.179 51.83,51.179 ccw(c51.83,51.299) 51.95,51.299 51.95,51.579 cw(c52,51.579) 52,51.629 52.271,51.629 53.4,50.5 54.4,50.5 ccw(c54.55,50.5) 54.7,50.5 55.45,50.5 ccw(c55.6,50.5) 55.75,50.5 56.35,50.5 cw(c56.5,50.5) 56.65,50.5 57.45,50.5 U8.T19@57.975,51.025
GMII_TX_ER: RA2.15 U8.R22 | length 12.6
  Top Layer w0.15: RA2.15@48.8,51.15 49.75,51.15 50.35,50.55 50.68,50.55 ccw(c50.68,50.67) 50.8,50.67 50.8,50.848 cw(c50.92,50.848) 50.92,50.968 50.98,50.968 cw(c50.98,50.848) 51.1,50.848 51.1,49.822 ccw(c51.22,49.822) 51.22,49.702 51.28,49.702 ccw(c51.28,49.822) 51.4,49.822 51.4,50.848 cw(c51.52,50.848) 51.52,50.968 51.58,50.968 cw(c51.58,50.848) 51.7,50.848 51.7,49.82 ccw(c51.82,49.82) 51.82,49.7 51.88,49.7 ccw(c51.88,49.82) 52,49.82 52,50.905 cw(c52.12,50.905) 52.12,51.025 52.18,51.025 cw(c52.18,50.905) 52.3,50.905 52.3,50.67 ccw(c52.42,50.67) 52.42,50.55 52.75,50.55 53.3,50 53.6,50 ccw(c53.75,50) 53.9,50 cw(c54.05,50) 54.2,50 ccw(c54.35,50) 54.5,50 U8.R22@55,50
GMII_TXD0: RA1.9 U8.T22 | length 12.4
  Top Layer w0.15: RA1.9@46.95,52.7 46.95,52.35 47.05,52.25 47.615,52.25 ccw(c47.615,52.385) 47.75,52.385 47.75,52.683 cw(c47.885,52.683) 47.885,52.818 47.915,52.818 cw(c47.915,52.683) 48.05,52.683 48.05,52.385 ccw(c48.185,52.385) 48.185,52.25 49.48,52.25 cw(c49.48,52.13) 49.6,52.13 49.6,52.02 ccw(c49.72,52.02) 49.72,51.9 49.78,51.9 ccw(c49.78,52.02) 49.9,52.02 49.9,52.13 cw(c50.02,52.13) 50.02,52.25 50.08,52.25 cw(c50.08,52.13) 50.2,52.13 50.2,52.02 ccw(c50.32,52.02) 50.32,51.9 50.38,51.9 ccw(c50.38,52.02) 50.5,52.02 50.5,52.13 cw(c50.62,52.13) 50.62,52.25 50.68,52.25 cw(c50.68,52.13) 50.8,52.13 50.8,52.02 ccw(c50.92,52.02) 50.92,51.9 50.98,51.9 ccw(c50.98,52.02) 51.1,52.02 51.1,52.13 cw(c51.22,52.13) 51.22,52.25 51.28,52.25 cw(c51.28,52.13) 51.4,52.13 51.4,52.02 ccw(c51.52,52.02) 51.52,51.9 51.58,51.9 ccw(c51.58,52.02) 51.7,52.02 51.7,52.13 cw(c51.82,52.13) 51.82,52.25 52.15,52.25 53.4,51 53.75,51 ccw(c53.9,51) 54.05,51 cw(c54.2,51) 54.35,51 ccw(c54.5,51) 54.65,51 U8.T22@55,51
GMII_TXD1: RA1.10 U8.T21 | length 12.4
  Top Layer w0.15: RA1.10@46.95,53.2 48,53.2 48.221,52.979 48.551,52.979 cw(c48.551,52.859) 48.671,52.859 48.671,52.749 ccw(c48.791,52.749) 48.791,52.629 48.851,52.629 ccw(c48.851,52.749) 48.971,52.749 48.971,52.859 cw(c49.091,52.859) 49.091,52.979 49.151,52.979 cw(c49.151,52.859) 49.271,52.859 49.271,52.749 ccw(c49.391,52.749) 49.391,52.629 49.451,52.629 ccw(c49.451,52.749) 49.571,52.749 49.571,52.859 cw(c49.691,52.859) 49.691,52.979 49.751,52.979 cw(c49.751,52.859) 49.871,52.859 49.871,52.749 ccw(c49.991,52.749) 49.991,52.629 50.051,52.629 ccw(c50.051,52.749) 50.171,52.749 50.171,52.859 cw(c50.291,52.859) 50.291,52.979 50.351,52.979 cw(c50.351,52.859) 50.471,52.859 50.471,52.749 ccw(c50.591,52.749) 50.591,52.629 50.651,52.629 ccw(c50.651,52.749) 50.771,52.749 50.771,52.859 cw(c50.891,52.859) 50.891,52.979 50.951,52.979 cw(c50.951,52.859) 51.071,52.859 51.071,52.749 ccw(c51.191,52.749) 51.191,52.629 51.251,52.629 ccw(c51.251,52.749) 51.371,52.749 51.371,52.859 cw(c51.491,52.859) 51.491,52.979 51.971,52.979 53.45,51.5 55.55,51.5 U8.T21@56.025,51.025
GMII_TXD2: RA1.11 U8.U22 | length 12.6
  Top Layer w0.15: RA1.11@46.95,53.7 48.38,53.7 cw(c48.38,53.58) 48.5,53.58 48.5,53.37 ccw(c48.62,53.37) 48.62,53.25 48.68,53.25 ccw(c48.68,53.37) 48.8,53.37 48.8,53.58 cw(c48.92,53.58) 48.92,53.7 48.98,53.7 cw(c48.98,53.58) 49.1,53.58 49.1,53.37 ccw(c49.22,53.37) 49.22,53.25 49.28,53.25 ccw(c49.28,53.37) 49.4,53.37 49.4,53.58 cw(c49.52,53.58) 49.52,53.7 49.58,53.7 cw(c49.58,53.58) 49.7,53.58 49.7,53.37 ccw(c49.82,53.37) 49.82,53.25 49.88,53.25 ccw(c49.88,53.37) 50,53.37 50,53.58 cw(c50.12,53.58) 50.12,53.7 50.18,53.7 cw(c50.18,53.58) 50.3,53.58 50.3,53.37 ccw(c50.42,53.37) 50.42,53.25 50.48,53.25 ccw(c50.48,53.37) 50.6,53.37 50.6,53.58 cw(c50.72,53.58) 50.72,53.7 50.78,53.7 cw(c50.78,53.58) 50.9,53.58 50.9,53.37 ccw(c51.02,53.37) 51.02,53.25 51.08,53.25 ccw(c51.08,53.37) 51.2,53.37 51.2,53.58 cw(c51.32,53.58) 51.32,53.7 51.75,53.7 53.45,52 53.8,52 cw(c53.95,52) 54.1,52 ccw(c54.25,52) 54.4,52 U8.U22@55,52
GMII_TXD3: RA1.12 U8.U20 | length 12.4
  Top Layer w0.15: RA1.12@46.95,54.2 47.565,54.2 ccw(c47.565,54.335) 47.7,54.335 47.7,54.365 cw(c47.835,54.365) 47.835,54.5 47.865,54.5 cw(c47.865,54.365) 48,54.365 48,54.335 ccw(c48.135,54.335) 48.135,54.2 48.165,54.2 ccw(c48.165,54.335) 48.3,54.335 48.3,54.365 cw(c48.435,54.365) 48.435,54.5 48.465,54.5 cw(c48.465,54.365) 48.6,54.365 48.6,54.335 ccw(c48.735,54.335) 48.735,54.2 48.765,54.2 ccw(c48.765,54.335) 48.9,54.335 48.9,54.365 cw(c49.035,54.365) 49.035,54.5 49.065,54.5 cw(c49.065,54.365) 49.2,54.365 49.2,54.335 ccw(c49.335,54.335) 49.335,54.2 49.365,54.2 ccw(c49.365,54.335) 49.5,54.335 49.5,54.365 cw(c49.635,54.365) 49.635,54.5 49.665,54.5 cw(c49.665,54.365) 49.8,54.365 49.8,54.335 ccw(c49.935,54.335) 49.935,54.2 51.604,54.2 52.154,53.65 52.35,53.65 53.5,52.5 56.5,52.5 U8.U20@57,52
GMII_TXD4: RA1.13 U8.V22 | length 12.3
  Top Layer w0.15: RA1.13@46.95,54.7 47.45,54.7 47.85,55.1 48.283,55.1 cw(c48.283,55.007) 48.375,55.007 ccw(c48.533,55.007) 48.533,54.85 48.568,54.85 ccw(c48.568,55.007) 48.725,55.007 48.725,55.192 cw(c48.883,55.192) 48.883,55.35 48.918,55.35 cw(c48.918,55.192) 49.075,55.192 49.075,55.007 ccw(c49.233,55.007) 49.233,54.85 49.268,54.85 ccw(c49.268,55.007) 49.425,55.007 49.425,55.192 cw(c49.583,55.192) 49.583,55.35 49.618,55.35 cw(c49.618,55.192) 49.775,55.192 49.775,55.007 ccw(c49.933,55.007) 49.933,54.85 49.968,54.85 ccw(c49.968,55.007) 50.125,55.007 cw(c50.218,55.007) 50.218,55.1 50.383,55.1 cw(c50.383,55.007) 50.475,55.007 ccw(c50.633,55.007) 50.633,54.85 50.668,54.85 ccw(c50.668,55.007) 50.825,55.007 cw(c50.918,55.007) 50.918,55.1 51.35,55.1 51.597,54.853 ccw(c51.721,54.729) 51.845,54.605 cw(c51.969,54.481) 52.092,54.358 ccw(c52.216,54.234) 52.34,54.11 cw(c52.464,53.986) 52.587,53.863 52.835,53.615 cw(c52.959,53.491) 53.082,53.368 53.45,53 53.8,53 ccw(c53.975,53) 54.15,53 U8.V22@55,53
GMII_TXD5: RA1.14 U8.V21 | length 12.5
  Top Layer w0.15: RA1.14@46.95,55.2 47.4,55.2 47.85,55.65 49.95,55.65 cw(c50.125,55.65) 50.3,55.65 ccw(c50.475,55.65) 50.65,55.65 cw(c50.825,55.65) 51,55.65 ccw(c51.175,55.65) 51.35,55.65 51.7,55.65 52.118,55.232 ccw(c52.241,55.109) 52.365,54.985 cw(c52.489,54.861) 52.613,54.737 ccw(c52.736,54.614) 52.86,54.49 cw(c52.984,54.366) 53.108,54.242 ccw(c53.231,54.119) 53.355,53.995 cw(c53.479,53.871) 53.603,53.747 53.85,53.5 54.3,53.5 ccw(c54.475,53.5) 54.65,53.5 55.45,53.5 U8.V21@55.975,52.975
GMII_TXD6: RA1.15 U8.W22 | length 12.4
  Top Layer w0.15: RA1.15@46.95,55.7 47.4,55.7 48.2,56.5 48.767,56.5 cw(c48.767,56.342) 48.925,56.342 48.925,56.158 ccw(c49.082,56.158) 49.082,56 49.117,56 ccw(c49.117,56.158) 49.275,56.158 49.275,56.342 cw(c49.432,56.342) 49.432,56.5 49.467,56.5 cw(c49.467,56.342) 49.625,56.342 49.625,56.158 ccw(c49.782,56.158) 49.782,56 49.817,56 ccw(c49.817,56.158) 49.975,56.158 49.975,56.342 cw(c50.132,56.342) 50.132,56.5 51.85,56.5 52.079,56.271 cw(c52.185,56.165) 52.291,56.059 ccw(c52.397,55.953) 52.503,55.847 cw(c52.609,55.741) 52.715,55.635 ccw(c52.821,55.529) 52.927,55.423 cw(c53.033,55.317) 53.139,55.211 ccw(c53.245,55.105) 53.351,54.999 cw(c53.458,54.892) 53.564,54.786 ccw(c53.67,54.68) 53.776,54.574 cw(c53.882,54.468) 53.988,54.362 54.35,54 U8.W22@55,54
GMII_TXD7: RA1.16 U8.W20 | length 12.7
  Top Layer w0.15: RA1.16@46.95,56.2 47.45,56.2 48.25,57 49.8,57 cw(c49.95,57) 50.1,57 ccw(c50.25,57) 50.4,57 cw(c50.55,57) 50.7,57 ccw(c50.85,57) 51,57 cw(c51.15,57) 51.3,57 ccw(c51.45,57) 51.6,57 52,57 54.5,54.5 56.5,54.5 U8.W20@57,54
